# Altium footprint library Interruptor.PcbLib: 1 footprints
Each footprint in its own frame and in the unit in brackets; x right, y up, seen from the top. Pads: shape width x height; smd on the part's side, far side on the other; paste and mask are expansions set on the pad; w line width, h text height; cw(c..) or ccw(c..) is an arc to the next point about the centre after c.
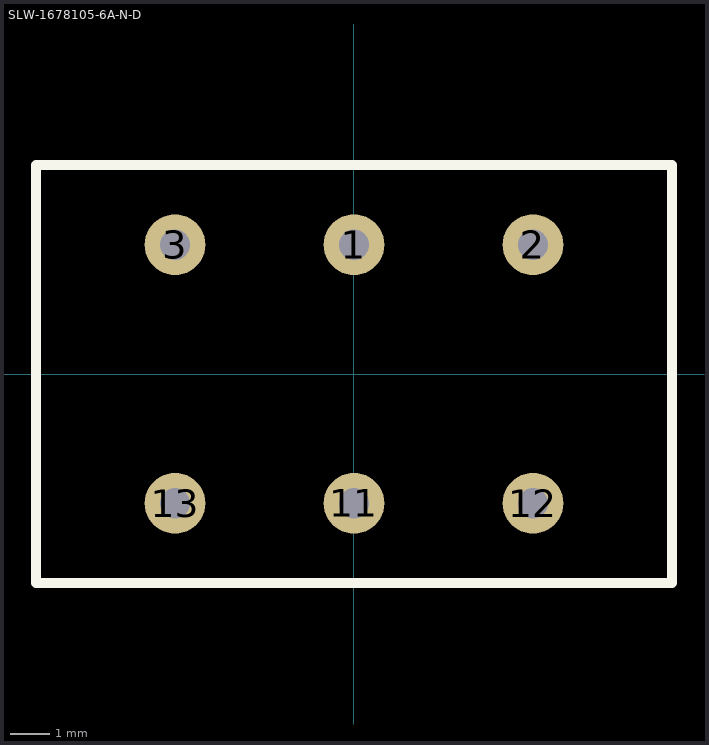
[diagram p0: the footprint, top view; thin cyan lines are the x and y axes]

## SLW-1678105-6A-N-D [mil] "Interruptor"
pads (6):
  round 60 hole 30: 1(0,127.95) 2(177.17,127.95) 3(-177.17,127.95) 11(0,-127.95) 12(177.17,-127.95) 13(-177.17,-127.95)
Top Overlay:
  lines w10: -314.96,-206.69 314.96,-206.69 314.96,206.69 -314.96,206.69 -314.96,-206.69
